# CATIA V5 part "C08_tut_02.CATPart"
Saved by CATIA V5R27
Part number: Part1
Bounding box of the stored display mesh (mm): x -50.5 to 34.99, y -44.802 to 44.802, z 0 to 30
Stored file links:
  E:\_Deepak\2017_Deepak\CATIA\Resources\Tutorial Files\Tutorials\c08_catia_v5_6r2016_tut\C08_tut_02.CATPart
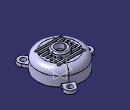
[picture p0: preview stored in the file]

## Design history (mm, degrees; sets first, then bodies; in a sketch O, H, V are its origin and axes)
Body1 (main body)
  Sketch1 on yz-plane, origin (0, 0, 0), H (0, 1, 0), V (0, 0, 1)
    line L1 (0, 0) -> (0, 25)
    line L2 (0, 25) -> (25, 25)
    point P2 (35, 25)
    line L3 (35, 15) -> (35, 0)
    point P3 (35, 0)
    line L4 (35, 0) -> (0, 0)
    reference intersected line E1 through (0, 0) direction (0, 1) from zx-plane
    axis line L5 (0, 41.2428) -> (0, -12.5007)
    point P4 (0, 41.2428)
    arc A1 centre (25, 15) radius 10 from (25, 25) to (35, 15) cw
    radius about axis P3 L5 = 35
    distance P2 P3 = 25
    radius A1 = 10
    horizontal: L2 H, L4 H
    coincidence: P3 H, L1 E1, P4 L1, L2 P2, L3 P2
    vertical: L3 V, L5 V
    tangency: A1 L2, A1 L3
  Shaft1: profile Sketch1, axis Sketch1.L5, angle 360
  Shell1: ExtOffset 0, Face face of Shaft1 from Sketch1.L4, IntOffset 3
  Sketch2 on face of Shaft1 from Sketch1.L4, origin (0, 0, 0), H (1, 0, 0), V (0, -1, 0)
    projected circle E1 centre (0, 0) radius 35 from edge [face of Shaft1 from Sketch1.L3 | face of Shaft1 from Sketch1.L4]
    projected arc E2 centre (0, 0) radius 35 from (-34.0735, 8) to (-34.0735, -8) ccw from edge [face of Shaft1 from Sketch1.L3 | face of Shaft1 from Sketch1.L4]
    point P1 (-34.0735, 8)
    line L1 (-34.0735, 8) -> (-42.5, 8)
    arc A1 centre (-42.5, 0) radius 8 from (-42.5, 8) to (-42.5, -8) ccw
    point P3 (-42.5, 0)
    line L2 (-42.5, -8) -> (-34.0735, -8)
    point P5 (-34.0735, -8)
    circle A2 centre (-42.5, 0) radius 4
    radius A1 = 8
    radius A2 = 4
    distance P3 V = 42.5
    coincidence: P1 E1, P3 H, P5 E1
    horizontal: L1 H, L2 H
    tangency: A1 L1, L2 A1
  Pad1: profile Sketch2, direction (0, 0, 1), length 5
  CircPattern1: of Pad1, instances 3, angular step 120 {= 360.0*1 deg/CircPattern1.AngularNumber}, axis from face of Shaft1 from Sketch1.L3
  Sketch3 on face of Shaft1 from Sketch1.L2, origin (0, 0, 25), H (1, 0, 0), V (0, 1, 0)
    point P1 (0, -18)
    line L1 (20, -19.75) -> (-20, -19.75)
    line L2 (-20, -16.25) -> (20, -16.25)
    point P5 (-20, -16.25)
    point P6 (20, -18)
    point P7 (-20, -18)
    arc A1 centre (20, -18) radius 1.75 from (20, -19.75) to (20, -16.25) ccw
    arc A2 centre (-20, -18) radius 1.75 from (-20, -16.25) to (-20, -19.75) ccw
    point P8 (-20, -16.25)
    axis line L3 (20, -18) -> (-20, -18)
    distance H P6 = 18
    distance L2 L1 = 3.5
    distance V P6 = 20
    coincidence: P1 V, A2 P5, P5 P8
    horizontal: L1 H, L2 H, L3 H
    equidistance: L1 L2 P1
    tangency: A1 L1, A2 L1, L2 A2, L2 A1
    symmetry: P7 P6 V
  Pocket1: profile Sketch3, direction (0, 0, -1), length 8
  RectPattern1: of Pocket1, direction 1 instances 7, spacing 6, along yz-plane
  Sketch4 on face of Shell1, origin (0, 0, 22), H (1, 0, 0), V (0, -1, 0)
    circle A1 centre (0, 0) radius 12.5
    radius A1 = 12.5
  Pad2: profile Sketch4, direction (0, 0, 1), length 8
  Sketch5 on face of Pad2, origin (0, 0, 22), H (1, 0, 0), V (0, -1, 0)
    circle A1 centre (0, 0) radius 7.5
    radius A1 = 7.5
  Pocket2: profile Sketch5, direction (0, 0, 1), length 8
  Fillet1: radius 2, on edge [end face of Pad2 | face of Pad2 from Sketch4.A1]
